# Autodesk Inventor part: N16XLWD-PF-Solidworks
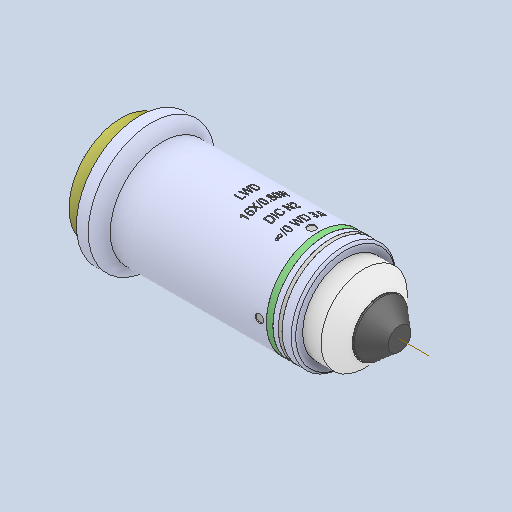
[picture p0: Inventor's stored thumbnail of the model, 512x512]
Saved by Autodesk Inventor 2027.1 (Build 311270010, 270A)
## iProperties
Created: 2012-05
Part Number: N16XLWD-PF-Solidworks
Material: Generic
Document SubType Name: Modeling
Designer: dunge
Density: 1 g/cm^3
Appearance: Default
Sending System: SOLIDWORKS 2018
Last Saved Date: 2019-08-20
last saved by: agonzalez
Author: dunge
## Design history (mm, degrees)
feature "23559-001-1-solid1"
feature "23559-001-1-solid2"
workpoint "Work Point1"
  workaxis "Work Axis1"
body "Solid1"
body "Solid2"
